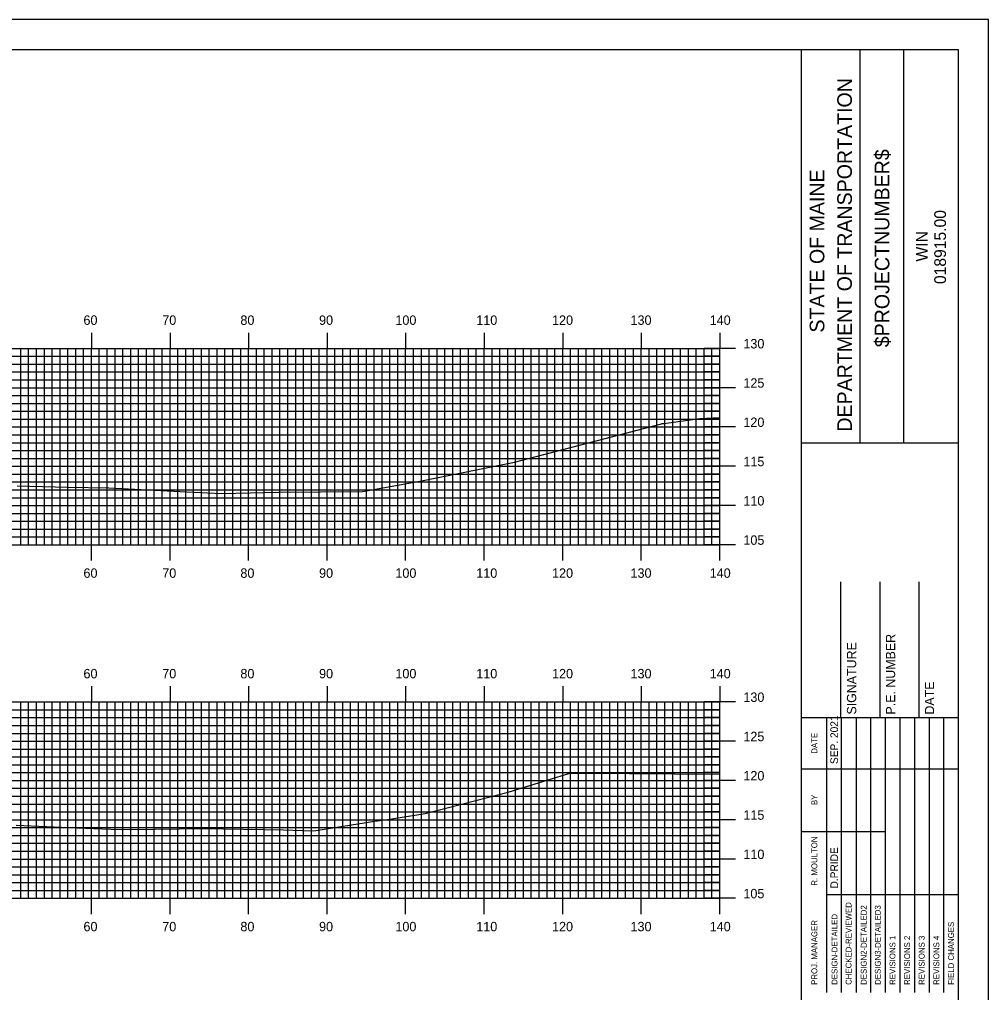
# Model space of a CAD drawing. Extents: x 1754314 to 1754654, y 442591 to 442811.
# Drawn here: x 1754530.8 to 1754654.2, y 442686.7 to 442810.5 of the extents above; entities that cross this region are included whole.
import ezdxf

# ---------------------------------------------------------------- set-up
doc = ezdxf.new("R2010")
doc.units = 0
for name, color, linetype in [('BORDER', 7, 'Continuous'), ('H_V ANNOTATION', 7, 'Continuous'), ('MAJOR', 7, 'Continuous'), ('MINOR', 7, 'Continuous'), ('PLOT BOUNDARY', 7, 'Continuous'), ('S_Roadway_Centerline', 7, 'Continuous')]:
    doc.layers.add(name, color=color, linetype=linetype)

msp = doc.modelspace()

# ---------------------------------------------------------------- linework, layer by layer
at = {"layer": 'BORDER'}
for p, q in [((1754630.4, 442596.67), (1754630.4, 442806.67)), ((1754637.86, 442756.66), (1754637.86, 442806.66)), ((1754643.45, 442756.66), (1754643.45, 442806.66)), ((1754630.41, 442756.65), (1754650.4, 442756.65)), ((1754635.4, 442721.67), (1754635.4, 442738.97)), ((1754640.4, 442721.67), (1754640.4, 442738.97)), ((1754645.4, 442721.67), (1754645.4, 442738.97)), ((1754630.4, 442721.67), (1754650.4, 442721.67))]:
    msp.add_line(p, q, dxfattribs=at)
msp.add_lwpolyline([(1754330.4, 442596.67), (1754650.4, 442596.67), (1754650.4, 442806.67), (1754330.4, 442806.67)], close=True, dxfattribs=at)
for points in [[(1754633.63, 442715.17), (1754633.63, 442721.67)], [(1754635.5, 442686.68), (1754635.5, 442721.67)], [(1754637.36, 442721.67), (1754637.36, 442686.68)], [(1754639.23, 442686.68), (1754639.23, 442721.67)], [(1754641.09, 442686.68), (1754641.09, 442721.67)], [(1754642.95, 442686.68), (1754642.95, 442721.67)], [(1754644.82, 442686.68), (1754644.82, 442721.67)], [(1754646.68, 442686.68), (1754646.68, 442721.67)], [(1754648.54, 442686.68), (1754648.54, 442721.67)], [(1754633.64, 442686.68), (1754633.64, 442720.26)], [(1754630.4, 442715.17), (1754650.4, 442715.17)], [(1754630.4, 442707.17), (1754633.64, 442707.17)], [(1754633.63, 442707.17), (1754641.09, 442707.17)], [(1754633.63, 442699.17), (1754650.4, 442699.17)]]:
    msp.add_lwpolyline(points, dxfattribs=at)
at = {"layer": 'MAJOR'}
for p, q in [((1754540, 442770.67), (1754540, 442768.67)), ((1754550, 442770.67), (1754550, 442768.67)), ((1754560, 442770.67), (1754560, 442768.67)), ((1754570, 442770.67), (1754570, 442768.67)), ((1754580, 442770.67), (1754580, 442768.67)), ((1754590, 442770.67), (1754590, 442768.67)), ((1754600, 442770.67), (1754600, 442768.67)), ((1754610, 442770.67), (1754610, 442768.67)), ((1754620, 442770.67), (1754620, 442768.67)), ((1754340, 442768.67), (1754620, 442768.67)), ((1754340, 442768.67), (1754620, 442768.67)), ((1754540, 442743.67), (1754540, 442768.67)), ((1754550, 442743.67), (1754550, 442768.67)), ((1754560, 442743.67), (1754560, 442768.67)), ((1754570, 442743.67), (1754570, 442768.67)), ((1754580, 442743.67), (1754580, 442768.67)), ((1754590, 442743.67), (1754590, 442768.67)), ((1754600, 442743.67), (1754600, 442768.67)), ((1754610, 442743.67), (1754610, 442768.67)), ((1754622.01, 442768.67), (1754618, 442768.67)), ((1754620, 442743.67), (1754620, 442768.67)), ((1754620, 442743.67), (1754620, 442768.67)), ((1754340, 442763.67), (1754620, 442763.67)), ((1754622.01, 442763.67), (1754618, 442763.67)), ((1754340, 442758.67), (1754620, 442758.67)), ((1754622.01, 442758.67), (1754618, 442758.67)), ((1754340, 442753.67), (1754620, 442753.67)), ((1754622.01, 442753.67), (1754618, 442753.67)), ((1754340, 442748.67), (1754620, 442748.67)), ((1754622.01, 442748.67), (1754618, 442748.67)), ((1754340, 442743.67), (1754620, 442743.67)), ((1754340, 442743.67), (1754620, 442743.67)), ((1754540, 442741.66), (1754540, 442743.67)), ((1754550, 442741.66), (1754550, 442743.67)), ((1754560, 442741.66), (1754560, 442743.67)), ((1754570, 442741.66), (1754570, 442743.67)), ((1754580, 442741.66), (1754580, 442743.67)), ((1754590, 442741.66), (1754590, 442743.67)), ((1754600, 442741.66), (1754600, 442743.67)), ((1754610, 442741.66), (1754610, 442743.67)), ((1754622.01, 442743.67), (1754618, 442743.67)), ((1754620, 442741.66), (1754620, 442743.67)), ((1754540, 442725.67), (1754540, 442723.67)), ((1754550, 442725.67), (1754550, 442723.67)), ((1754560, 442725.67), (1754560, 442723.67)), ((1754570, 442725.67), (1754570, 442723.67)), ((1754580, 442725.67), (1754580, 442723.67)), ((1754590, 442725.67), (1754590, 442723.67)), ((1754600, 442725.67), (1754600, 442723.67)), ((1754610, 442725.67), (1754610, 442723.67)), ((1754620, 442725.67), (1754620, 442723.67)), ((1754340, 442723.67), (1754620, 442723.67)), ((1754340, 442723.67), (1754620, 442723.67)), ((1754540, 442698.67), (1754540, 442723.67)), ((1754550, 442698.67), (1754550, 442723.67)), ((1754560, 442698.67), (1754560, 442723.67)), ((1754570, 442698.67), (1754570, 442723.67)), ((1754580, 442698.67), (1754580, 442723.67)), ((1754590, 442698.67), (1754590, 442723.67)), ((1754600, 442698.67), (1754600, 442723.67)), ((1754610, 442698.67), (1754610, 442723.67)), ((1754622.01, 442723.67), (1754618, 442723.67)), ((1754620, 442698.67), (1754620, 442723.67)), ((1754620, 442698.67), (1754620, 442723.67)), ((1754340, 442718.67), (1754620, 442718.67)), ((1754622.01, 442718.67), (1754618, 442718.67)), ((1754340, 442713.67), (1754620, 442713.67)), ((1754622.01, 442713.67), (1754618, 442713.67)), ((1754340, 442708.67), (1754620, 442708.67)), ((1754622.01, 442708.67), (1754618, 442708.67)), ((1754340, 442703.67), (1754620, 442703.67)), ((1754622.01, 442703.67), (1754618, 442703.67)), ((1754340, 442698.67), (1754620, 442698.67)), ((1754340, 442698.67), (1754620, 442698.67)), ((1754540, 442696.66), (1754540, 442698.67)), ((1754550, 442696.66), (1754550, 442698.67)), ((1754560, 442696.66), (1754560, 442698.67)), ((1754570, 442696.66), (1754570, 442698.67)), ((1754580, 442696.66), (1754580, 442698.67)), ((1754590, 442696.66), (1754590, 442698.67)), ((1754600, 442696.66), (1754600, 442698.67)), ((1754610, 442696.66), (1754610, 442698.67)), ((1754622.01, 442698.67), (1754618, 442698.67)), ((1754620, 442696.66), (1754620, 442698.67))]:
    msp.add_line(p, q, dxfattribs=at)
at = {"layer": 'MINOR'}
for p, q in [((1754531, 442743.67), (1754531, 442768.67)), ((1754532, 442743.67), (1754532, 442768.67)), ((1754533, 442743.67), (1754533, 442768.67)), ((1754534, 442743.67), (1754534, 442768.67)), ((1754535, 442743.67), (1754535, 442768.67)), ((1754536, 442743.67), (1754536, 442768.67)), ((1754537, 442743.67), (1754537, 442768.67)), ((1754538, 442743.67), (1754538, 442768.67)), ((1754539, 442743.67), (1754539, 442768.67)), ((1754541, 442743.67), (1754541, 442768.67)), ((1754542, 442743.67), (1754542, 442768.67)), ((1754543, 442743.67), (1754543, 442768.67)), ((1754544, 442743.67), (1754544, 442768.67)), ((1754545, 442743.67), (1754545, 442768.67)), ((1754546, 442743.67), (1754546, 442768.67)), ((1754547, 442743.67), (1754547, 442768.67)), ((1754548, 442743.67), (1754548, 442768.67)), ((1754549, 442743.67), (1754549, 442768.67)), ((1754551, 442743.67), (1754551, 442768.67)), ((1754552, 442743.67), (1754552, 442768.67)), ((1754553, 442743.67), (1754553, 442768.67)), ((1754554, 442743.67), (1754554, 442768.67)), ((1754555, 442743.67), (1754555, 442768.67)), ((1754556, 442743.67), (1754556, 442768.67)), ((1754557, 442743.67), (1754557, 442768.67)), ((1754558, 442743.67), (1754558, 442768.67)), ((1754559, 442743.67), (1754559, 442768.67)), ((1754561, 442743.67), (1754561, 442768.67)), ((1754562, 442743.67), (1754562, 442768.67)), ((1754563, 442743.67), (1754563, 442768.67)), ((1754564, 442743.67), (1754564, 442768.67)), ((1754565, 442743.67), (1754565, 442768.67)), ((1754566, 442743.67), (1754566, 442768.67)), ((1754567, 442743.67), (1754567, 442768.67)), ((1754568, 442743.67), (1754568, 442768.67)), ((1754569, 442743.67), (1754569, 442768.67)), ((1754571, 442743.67), (1754571, 442768.67)), ((1754572, 442743.67), (1754572, 442768.67)), ((1754573, 442743.67), (1754573, 442768.67)), ((1754574, 442743.67), (1754574, 442768.67)), ((1754575, 442743.67), (1754575, 442768.67)), ((1754576, 442743.67), (1754576, 442768.67)), ((1754577, 442743.67), (1754577, 442768.67)), ((1754578, 442743.67), (1754578, 442768.67)), ((1754579, 442743.67), (1754579, 442768.67)), ((1754581, 442743.67), (1754581, 442768.67)), ((1754582, 442743.67), (1754582, 442768.67)), ((1754583, 442743.67), (1754583, 442768.67)), ((1754584, 442743.67), (1754584, 442768.67)), ((1754585, 442743.67), (1754585, 442768.67)), ((1754586, 442743.67), (1754586, 442768.67)), ((1754587, 442743.67), (1754587, 442768.67)), ((1754588, 442743.67), (1754588, 442768.67)), ((1754589, 442743.67), (1754589, 442768.67)), ((1754591, 442743.67), (1754591, 442768.67)), ((1754592, 442743.67), (1754592, 442768.67)), ((1754593, 442743.67), (1754593, 442768.67)), ((1754594, 442743.67), (1754594, 442768.67)), ((1754595, 442743.67), (1754595, 442768.67)), ((1754596, 442743.67), (1754596, 442768.67)), ((1754597, 442743.67), (1754597, 442768.67)), ((1754598, 442743.67), (1754598, 442768.67)), ((1754599, 442743.67), (1754599, 442768.67)), ((1754601, 442743.67), (1754601, 442768.67)), ((1754602, 442743.67), (1754602, 442768.67)), ((1754603, 442743.67), (1754603, 442768.67)), ((1754604, 442743.67), (1754604, 442768.67)), ((1754605, 442743.67), (1754605, 442768.67)), ((1754606, 442743.67), (1754606, 442768.67)), ((1754607, 442743.67), (1754607, 442768.67)), ((1754608, 442743.67), (1754608, 442768.67)), ((1754609, 442743.67), (1754609, 442768.67)), ((1754611, 442743.67), (1754611, 442768.67)), ((1754612, 442743.67), (1754612, 442768.67)), ((1754613, 442743.67), (1754613, 442768.67)), ((1754614, 442743.67), (1754614, 442768.67)), ((1754615, 442743.67), (1754615, 442768.67)), ((1754616, 442743.67), (1754616, 442768.67)), ((1754617, 442743.67), (1754617, 442768.67)), ((1754618, 442743.67), (1754618, 442768.67)), ((1754619, 442743.67), (1754619, 442768.67)), ((1754340, 442767.67), (1754620, 442767.67)), ((1754620, 442767.67), (1754618, 442767.67)), ((1754340, 442766.67), (1754620, 442766.67)), ((1754620, 442766.67), (1754618, 442766.67)), ((1754340, 442765.67), (1754620, 442765.67)), ((1754620, 442765.67), (1754618, 442765.67)), ((1754340, 442764.67), (1754620, 442764.67)), ((1754620, 442764.67), (1754618, 442764.67)), ((1754340, 442762.67), (1754620, 442762.67)), ((1754620, 442762.67), (1754618, 442762.67)), ((1754340, 442761.67), (1754620, 442761.67)), ((1754620, 442761.67), (1754618, 442761.67)), ((1754340, 442760.67), (1754620, 442760.67)), ((1754620, 442760.67), (1754618, 442760.67)), ((1754340, 442759.67), (1754620, 442759.67)), ((1754620, 442759.67), (1754618, 442759.67)), ((1754340, 442757.67), (1754620, 442757.67)), ((1754620, 442757.67), (1754618, 442757.67)), ((1754340, 442756.67), (1754620, 442756.67)), ((1754620, 442756.67), (1754618, 442756.67)), ((1754340, 442755.67), (1754620, 442755.67)), ((1754620, 442755.67), (1754618, 442755.67)), ((1754340, 442754.67), (1754620, 442754.67)), ((1754620, 442754.67), (1754618, 442754.67)), ((1754340, 442752.67), (1754620, 442752.67)), ((1754620, 442752.67), (1754618, 442752.67)), ((1754340, 442751.67), (1754620, 442751.67)), ((1754620, 442751.67), (1754618, 442751.67)), ((1754340, 442750.67), (1754620, 442750.67)), ((1754620, 442750.67), (1754618, 442750.67)), ((1754340, 442749.67), (1754620, 442749.67)), ((1754620, 442749.67), (1754618, 442749.67)), ((1754340, 442747.67), (1754620, 442747.67)), ((1754620, 442747.67), (1754618, 442747.67)), ((1754340, 442746.67), (1754620, 442746.67)), ((1754620, 442746.67), (1754618, 442746.67)), ((1754340, 442745.67), (1754620, 442745.67)), ((1754620, 442745.67), (1754618, 442745.67)), ((1754340, 442744.67), (1754620, 442744.67)), ((1754620, 442744.67), (1754618, 442744.67)), ((1754531, 442698.67), (1754531, 442723.67)), ((1754532, 442698.67), (1754532, 442723.67)), ((1754533, 442698.67), (1754533, 442723.67)), ((1754534, 442698.67), (1754534, 442723.67)), ((1754535, 442698.67), (1754535, 442723.67)), ((1754536, 442698.67), (1754536, 442723.67)), ((1754537, 442698.67), (1754537, 442723.67)), ((1754538, 442698.67), (1754538, 442723.67)), ((1754539, 442698.67), (1754539, 442723.67)), ((1754541, 442698.67), (1754541, 442723.67)), ((1754542, 442698.67), (1754542, 442723.67)), ((1754543, 442698.67), (1754543, 442723.67)), ((1754544, 442698.67), (1754544, 442723.67)), ((1754545, 442698.67), (1754545, 442723.67)), ((1754546, 442698.67), (1754546, 442723.67)), ((1754547, 442698.67), (1754547, 442723.67)), ((1754548, 442698.67), (1754548, 442723.67)), ((1754549, 442698.67), (1754549, 442723.67)), ((1754551, 442698.67), (1754551, 442723.67)), ((1754552, 442698.67), (1754552, 442723.67)), ((1754553, 442698.67), (1754553, 442723.67)), ((1754554, 442698.67), (1754554, 442723.67)), ((1754555, 442698.67), (1754555, 442723.67)), ((1754556, 442698.67), (1754556, 442723.67)), ((1754557, 442698.67), (1754557, 442723.67)), ((1754558, 442698.67), (1754558, 442723.67)), ((1754559, 442698.67), (1754559, 442723.67)), ((1754561, 442698.67), (1754561, 442723.67)), ((1754562, 442698.67), (1754562, 442723.67)), ((1754563, 442698.67), (1754563, 442723.67)), ((1754564, 442698.67), (1754564, 442723.67)), ((1754565, 442698.67), (1754565, 442723.67)), ((1754566, 442698.67), (1754566, 442723.67)), ((1754567, 442698.67), (1754567, 442723.67)), ((1754568, 442698.67), (1754568, 442723.67)), ((1754569, 442698.67), (1754569, 442723.67)), ((1754571, 442698.67), (1754571, 442723.67)), ((1754572, 442698.67), (1754572, 442723.67)), ((1754573, 442698.67), (1754573, 442723.67)), ((1754574, 442698.67), (1754574, 442723.67)), ((1754575, 442698.67), (1754575, 442723.67)), ((1754576, 442698.67), (1754576, 442723.67)), ((1754577, 442698.67), (1754577, 442723.67)), ((1754578, 442698.67), (1754578, 442723.67)), ((1754579, 442698.67), (1754579, 442723.67)), ((1754581, 442698.67), (1754581, 442723.67)), ((1754582, 442698.67), (1754582, 442723.67)), ((1754583, 442698.67), (1754583, 442723.67)), ((1754584, 442698.67), (1754584, 442723.67)), ((1754585, 442698.67), (1754585, 442723.67)), ((1754586, 442698.67), (1754586, 442723.67)), ((1754587, 442698.67), (1754587, 442723.67)), ((1754588, 442698.67), (1754588, 442723.67)), ((1754589, 442698.67), (1754589, 442723.67)), ((1754591, 442698.67), (1754591, 442723.67)), ((1754592, 442698.67), (1754592, 442723.67)), ((1754593, 442698.67), (1754593, 442723.67)), ((1754594, 442698.67), (1754594, 442723.67)), ((1754595, 442698.67), (1754595, 442723.67)), ((1754596, 442698.67), (1754596, 442723.67)), ((1754597, 442698.67), (1754597, 442723.67)), ((1754598, 442698.67), (1754598, 442723.67)), ((1754599, 442698.67), (1754599, 442723.67)), ((1754601, 442698.67), (1754601, 442723.67)), ((1754602, 442698.67), (1754602, 442723.67)), ((1754603, 442698.67), (1754603, 442723.67)), ((1754604, 442698.67), (1754604, 442723.67)), ((1754605, 442698.67), (1754605, 442723.67)), ((1754606, 442698.67), (1754606, 442723.67)), ((1754607, 442698.67), (1754607, 442723.67)), ((1754608, 442698.67), (1754608, 442723.67)), ((1754609, 442698.67), (1754609, 442723.67)), ((1754611, 442698.67), (1754611, 442723.67)), ((1754612, 442698.67), (1754612, 442723.67)), ((1754613, 442698.67), (1754613, 442723.67)), ((1754614, 442698.67), (1754614, 442723.67)), ((1754615, 442698.67), (1754615, 442723.67)), ((1754616, 442698.67), (1754616, 442723.67)), ((1754617, 442698.67), (1754617, 442723.67)), ((1754618, 442698.67), (1754618, 442723.67)), ((1754619, 442698.67), (1754619, 442723.67)), ((1754340, 442722.67), (1754620, 442722.67)), ((1754340, 442721.67), (1754620, 442721.67)), ((1754620, 442722.67), (1754618, 442722.67)), ((1754620, 442721.67), (1754618, 442721.67)), ((1754340, 442720.67), (1754620, 442720.67)), ((1754620, 442720.67), (1754618, 442720.67)), ((1754340, 442719.67), (1754620, 442719.67)), ((1754620, 442719.67), (1754618, 442719.67)), ((1754340, 442717.67), (1754620, 442717.67)), ((1754340, 442716.67), (1754620, 442716.67)), ((1754620, 442717.67), (1754618, 442717.67)), ((1754620, 442716.67), (1754618, 442716.67)), ((1754340, 442715.67), (1754620, 442715.67)), ((1754620, 442715.67), (1754618, 442715.67)), ((1754340, 442714.67), (1754620, 442714.67)), ((1754620, 442714.67), (1754618, 442714.67)), ((1754340, 442712.67), (1754620, 442712.67)), ((1754340, 442711.67), (1754620, 442711.67)), ((1754620, 442712.67), (1754618, 442712.67)), ((1754620, 442711.67), (1754618, 442711.67)), ((1754340, 442710.67), (1754620, 442710.67)), ((1754620, 442710.67), (1754618, 442710.67)), ((1754340, 442709.67), (1754620, 442709.67)), ((1754620, 442709.67), (1754618, 442709.67)), ((1754340, 442707.67), (1754620, 442707.67)), ((1754340, 442706.67), (1754620, 442706.67)), ((1754620, 442707.67), (1754618, 442707.67)), ((1754620, 442706.67), (1754618, 442706.67)), ((1754340, 442705.67), (1754620, 442705.67)), ((1754620, 442705.67), (1754618, 442705.67)), ((1754340, 442704.67), (1754620, 442704.67)), ((1754620, 442704.67), (1754618, 442704.67)), ((1754340, 442702.67), (1754620, 442702.67)), ((1754340, 442701.67), (1754620, 442701.67)), ((1754620, 442702.67), (1754618, 442702.67)), ((1754620, 442701.67), (1754618, 442701.67)), ((1754340, 442700.67), (1754620, 442700.67)), ((1754620, 442700.67), (1754618, 442700.67)), ((1754340, 442699.67), (1754620, 442699.67)), ((1754620, 442699.67), (1754618, 442699.67))]:
    msp.add_line(p, q, dxfattribs=at)
at = {"layer": 'PLOT BOUNDARY'}
msp.add_lwpolyline([(1754314.22, 442590.55), (1754654.22, 442590.55), (1754654.22, 442810.55), (1754314.22, 442810.55)], close=True, dxfattribs=at)
at = {"layer": 'S_Roadway_Centerline'}
for points in [[(1754530.52, 442751.19), (1754536.97, 442751.01), (1754542.21, 442750.91), (1754551.31, 442750.45), (1754554.77, 442750.28), (1754556.61, 442750.22), (1754563.82, 442750.38), (1754574.49, 442750.47), (1754581.79, 442751.77), (1754593.87, 442754.2), (1754601.15, 442756.1), (1754612.58, 442759.09), (1754612.64, 442759.1), (1754612.86, 442759.13), (1754617.47, 442759.77), (1754620, 442759.86)], [(1754530.43, 442707.96), (1754538.14, 442707.62), (1754542.48, 442707.46), (1754545.07, 442707.45), (1754554.23, 442707.55), (1754564.44, 442707.38), (1754566.85, 442707.3), (1754568.31, 442707.26), (1754575.78, 442708.46), (1754577.69, 442708.69), (1754582.5, 442709.46), (1754593.07, 442712.19), (1754600.89, 442714.59), (1754602.14, 442714.6), (1754602.73, 442714.62), (1754620, 442714.46)]]:
    msp.add_lwpolyline(points, dxfattribs=at)

# ---------------------------------------------------------------- texts
at = {"layer": 'BORDER'}
for s, height, p in [('DEPARTMENT OF TRANSPORTATION', 1.8635, (1754636.82, 442758.08)), ('$PROJECTNUMBER$', 1.8635, (1754641.59, 442768.82)), ('STATE OF MAINE', 1.8635, (1754633.31, 442770.69)), ('018915.00', 1.491, (1754648.8, 442776.86)), ('WIN', 1.491, (1754646.48, 442779.73)), ('P.E. NUMBER', 1.1811, (1754642.33, 442722.06)), ('SIGNATURE', 1.181, (1754637.37, 442722.06)), ('DATE', 1.181, (1754647.29, 442722.06)), ('SEP. 2021', 0.969, (1754635.05, 442715.76)), ('DATE', 0.743, (1754632.41, 442717.08)), ('BY', 0.743, (1754632.41, 442710.54)), ('R. MOULTON', 0.745, (1754632.41, 442700.28)), ('D.PRIDE', 0.969, (1754635.05, 442699.92)), ('CHECKED-REVIEWED', 0.7455, (1754636.77, 442687.65)), ('DESIGN2-DETAILED2', 0.7455, (1754638.7, 442687.65)), ('DESIGN3-DETAILED3', 0.7455, (1754640.49, 442687.65)), ('PROJ. MANAGER', 0.7455, (1754632.41, 442687.65)), ('DESIGN-DETAILED', 0.7455, (1754634.98, 442687.65)), ('FIELD CHANGES', 0.7455, (1754649.81, 442687.65)), ('REVISIONS 1', 0.7455, (1754642.36, 442687.65)), ('REVISIONS 2', 0.7455, (1754644.22, 442687.65)), ('REVISIONS 3', 0.7455, (1754646.08, 442687.65)), ('REVISIONS 4', 0.7455, (1754647.95, 442687.65))]:
    msp.add_text(s, height=height, rotation=90, dxfattribs=at).set_placement(p)
at = {"layer": 'H_V ANNOTATION'}
for s, p in [('60', (1754538.98, 442771.67)), ('70', (1754549.01, 442771.67)), ('80', (1754558.96, 442771.67)), ('90', (1754568.98, 442771.67)), ('100', (1754578.69, 442771.67)), ('110', (1754588.99, 442771.67)), ('120', (1754598.64, 442771.67)), ('130', (1754608.63, 442771.67)), ('140', (1754618.71, 442771.67)), ('130', (1754623, 442768.67)), ('125', (1754623, 442763.67)), ('120', (1754623, 442758.67)), ('115', (1754623, 442753.67)), ('110', (1754623, 442748.67)), ('105', (1754623, 442743.67)), ('60', (1754538.98, 442739.47)), ('70', (1754549.01, 442739.47)), ('80', (1754558.96, 442739.47)), ('90', (1754568.98, 442739.47)), ('100', (1754578.69, 442739.47)), ('110', (1754588.99, 442739.47)), ('120', (1754598.64, 442739.47)), ('130', (1754608.63, 442739.47)), ('140', (1754618.71, 442739.47)), ('60', (1754538.98, 442726.67)), ('70', (1754549.01, 442726.67)), ('80', (1754558.96, 442726.67)), ('90', (1754568.98, 442726.67)), ('100', (1754578.69, 442726.67)), ('110', (1754588.99, 442726.67)), ('120', (1754598.64, 442726.67)), ('130', (1754608.63, 442726.67)), ('140', (1754618.71, 442726.67)), ('130', (1754623, 442723.67)), ('125', (1754623, 442718.67)), ('120', (1754623, 442713.67)), ('115', (1754623, 442708.67)), ('110', (1754623, 442703.67)), ('105', (1754623, 442698.67)), ('60', (1754538.98, 442694.47)), ('70', (1754549.01, 442694.47)), ('80', (1754558.96, 442694.47)), ('90', (1754568.98, 442694.47)), ('100', (1754578.69, 442694.47)), ('110', (1754588.99, 442694.47)), ('120', (1754598.64, 442694.47)), ('130', (1754608.63, 442694.47)), ('140', (1754618.71, 442694.47))]:
    msp.add_text(s, height=1.2, dxfattribs=at).set_placement(p)

doc.saveas('drawing.dxf')
